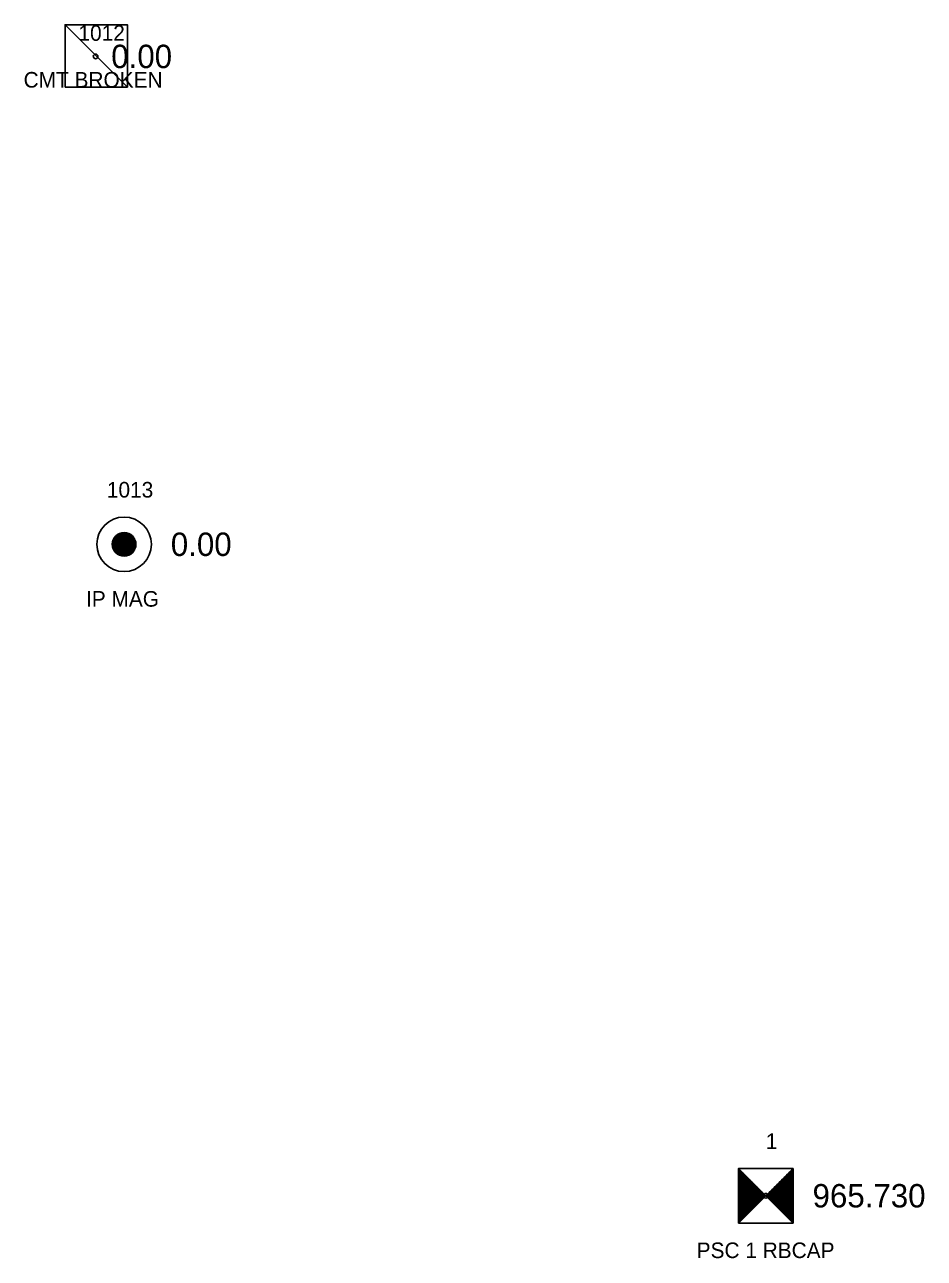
# Model space of a CAD drawing. Extents: x 1393163 to 1398407, y 1072670 to 1074651.
# Drawn here: x 1398130.1 to 1398187.8, y 1073408.2 to 1073487.3 of the extents above; entities that cross this region are included whole.
import ezdxf

# ---------------------------------------------------------------- set-up
doc = ezdxf.new("R2010")
doc.units = 0
for name, color, linetype in [('RD_EX_DV_Prop_txCode', 7, 'Continuous'), ('RD_EX_DV_PropPin', 7, 'Continuous'), ('RD_EX_TX_DV_Prop_ELEV', 7, 'Continuous'), ('RD_HC_Survey', 7, 'Continuous'), ('RD_HC_Survey_ELEV', 7, 'Continuous'), ('RD_HC_txCode', 7, 'Continuous'), ('RD_SMD_Locator', 7, 'Continuous')]:
    doc.layers.add(name, color=color, linetype=linetype)

msp = doc.modelspace()

# ---------------------------------------------------------------- linework, layer by layer
at = {"layer": 'RD_EX_DV_PropPin'}
for p, q in [((1398136.68, 1073483.307), (1398132.68, 1073487.307)), ((1398135.728, 1073453.781), (1398135.728, 1073454.174)), ((1398135.763, 1073453.679), (1398135.763, 1073454.275)), ((1398135.798, 1073453.608), (1398135.798, 1073454.347)), ((1398135.833, 1073453.551), (1398135.833, 1073454.404)), ((1398135.868, 1073453.503), (1398135.868, 1073454.452)), ((1398135.903, 1073453.462), (1398135.903, 1073454.492)), ((1398135.938, 1073453.427), (1398135.938, 1073454.528)), ((1398135.973, 1073453.395), (1398135.973, 1073454.56)), ((1398136.008, 1073453.368), (1398136.008, 1073454.587)), ((1398136.043, 1073453.343), (1398136.043, 1073454.612)), ((1398136.078, 1073453.321), (1398136.078, 1073454.634)), ((1398136.113, 1073453.302), (1398136.113, 1073454.653)), ((1398136.148, 1073453.285), (1398136.148, 1073454.67)), ((1398136.183, 1073453.27), (1398136.183, 1073454.685)), ((1398136.218, 1073453.257), (1398136.218, 1073454.698)), ((1398136.253, 1073453.246), (1398136.253, 1073454.709)), ((1398136.288, 1073453.237), (1398136.288, 1073454.718)), ((1398136.323, 1073453.229), (1398136.323, 1073454.725)), ((1398136.358, 1073453.224), (1398136.358, 1073454.731)), ((1398136.393, 1073453.22), (1398136.393, 1073454.735)), ((1398136.428, 1073453.217), (1398136.428, 1073454.738)), ((1398136.463, 1073453.216), (1398136.463, 1073454.738)), ((1398136.498, 1073453.217), (1398136.498, 1073454.738)), ((1398136.533, 1073453.22), (1398136.533, 1073454.735)), ((1398136.568, 1073453.224), (1398136.568, 1073454.731)), ((1398136.603, 1073453.229), (1398136.603, 1073454.725)), ((1398136.638, 1073453.237), (1398136.638, 1073454.718)), ((1398136.673, 1073453.246), (1398136.673, 1073454.709)), ((1398136.708, 1073453.257), (1398136.708, 1073454.698)), ((1398136.743, 1073453.27), (1398136.743, 1073454.685)), ((1398136.778, 1073453.285), (1398136.778, 1073454.67)), ((1398136.813, 1073453.302), (1398136.813, 1073454.653)), ((1398136.848, 1073453.321), (1398136.848, 1073454.634)), ((1398136.883, 1073453.343), (1398136.883, 1073454.612)), ((1398136.918, 1073453.368), (1398136.918, 1073454.587)), ((1398136.953, 1073453.395), (1398136.953, 1073454.56)), ((1398136.988, 1073453.427), (1398136.988, 1073454.528)), ((1398137.023, 1073453.462), (1398137.023, 1073454.492)), ((1398137.058, 1073453.503), (1398137.058, 1073454.452)), ((1398137.093, 1073453.551), (1398137.093, 1073454.404)), ((1398137.128, 1073453.608), (1398137.128, 1073454.347)), ((1398137.163, 1073453.679), (1398137.163, 1073454.275)), ((1398137.198, 1073453.781), (1398137.198, 1073454.174))]:
    msp.add_line(p, q, dxfattribs=at)
msp.add_lwpolyline([(1398132.68, 1073483.307), (1398132.68, 1073487.307), (1398136.68, 1073487.307), (1398136.68, 1073483.307)], close=True, dxfattribs=at)
for radius in [1.75, 0.761]:
    msp.add_circle((1398136.463, 1073453.977), radius, dxfattribs=at)
at = {"layer": 'RD_HC_Survey'}
for p, q in [((1398175.884, 1073413.941), (1398179.383, 1073410.442)), ((1398179.383, 1073413.941), (1398175.884, 1073410.442)), ((1398175.908, 1073413.917), (1398175.908, 1073410.466)), ((1398175.933, 1073413.892), (1398175.933, 1073410.491)), ((1398175.958, 1073413.867), (1398175.958, 1073410.516)), ((1398175.983, 1073413.842), (1398175.983, 1073410.541)), ((1398176.007, 1073413.818), (1398176.007, 1073410.565)), ((1398176.032, 1073413.793), (1398176.032, 1073410.59)), ((1398176.057, 1073413.768), (1398176.057, 1073410.615)), ((1398176.081, 1073413.744), (1398176.081, 1073410.639)), ((1398176.106, 1073413.719), (1398176.106, 1073410.664)), ((1398176.131, 1073413.694), (1398176.131, 1073410.689)), ((1398176.156, 1073413.669), (1398176.156, 1073410.714)), ((1398176.18, 1073413.645), (1398176.18, 1073410.738)), ((1398179.087, 1073413.645), (1398179.087, 1073410.738)), ((1398179.111, 1073413.669), (1398179.111, 1073410.714)), ((1398179.136, 1073413.694), (1398179.136, 1073410.689)), ((1398179.161, 1073413.719), (1398179.161, 1073410.664)), ((1398179.186, 1073413.744), (1398179.186, 1073410.639)), ((1398179.21, 1073413.768), (1398179.21, 1073410.615)), ((1398179.235, 1073413.793), (1398179.235, 1073410.59)), ((1398179.26, 1073413.818), (1398179.26, 1073410.565)), ((1398179.284, 1073413.842), (1398179.284, 1073410.541)), ((1398179.309, 1073413.867), (1398179.309, 1073410.516)), ((1398179.334, 1073413.892), (1398179.334, 1073410.491)), ((1398179.359, 1073413.917), (1398179.359, 1073410.466)), ((1398176.205, 1073413.62), (1398176.205, 1073410.763)), ((1398176.23, 1073413.595), (1398176.23, 1073410.788)), ((1398176.255, 1073413.57), (1398176.255, 1073410.813)), ((1398176.279, 1073413.546), (1398176.279, 1073410.837)), ((1398176.304, 1073413.521), (1398176.304, 1073410.862)), ((1398176.329, 1073413.496), (1398176.329, 1073410.887)), ((1398176.354, 1073413.471), (1398176.354, 1073410.912)), ((1398176.378, 1073413.447), (1398176.378, 1073410.936)), ((1398176.403, 1073413.422), (1398176.403, 1073410.961)), ((1398176.428, 1073413.397), (1398176.428, 1073410.986)), ((1398176.453, 1073413.372), (1398176.453, 1073411.011)), ((1398176.477, 1073413.348), (1398176.477, 1073411.035)), ((1398176.502, 1073413.323), (1398176.502, 1073411.06)), ((1398176.527, 1073413.298), (1398176.527, 1073411.085)), ((1398176.552, 1073413.273), (1398176.552, 1073411.11)), ((1398176.576, 1073413.249), (1398176.576, 1073411.134)), ((1398176.601, 1073413.224), (1398176.601, 1073411.159)), ((1398176.626, 1073413.199), (1398176.626, 1073411.184)), ((1398176.651, 1073413.174), (1398176.651, 1073411.209)), ((1398176.675, 1073413.15), (1398176.675, 1073411.233)), ((1398176.7, 1073413.125), (1398176.7, 1073411.258)), ((1398176.725, 1073413.1), (1398176.725, 1073411.283)), ((1398176.75, 1073413.075), (1398176.75, 1073411.308)), ((1398176.774, 1073413.051), (1398176.774, 1073411.332)), ((1398176.799, 1073413.026), (1398176.799, 1073411.357)), ((1398176.824, 1073413.001), (1398176.824, 1073411.382)), ((1398176.849, 1073412.976), (1398176.849, 1073411.407)), ((1398176.873, 1073412.952), (1398176.873, 1073411.431)), ((1398176.898, 1073412.927), (1398176.898, 1073411.456)), ((1398176.923, 1073412.902), (1398176.923, 1073411.481)), ((1398176.948, 1073412.877), (1398176.948, 1073411.506)), ((1398176.972, 1073412.853), (1398176.972, 1073411.53)), ((1398178.295, 1073412.853), (1398178.295, 1073411.53)), ((1398178.319, 1073412.877), (1398178.319, 1073411.506)), ((1398178.344, 1073412.902), (1398178.344, 1073411.481)), ((1398178.369, 1073412.927), (1398178.369, 1073411.456)), ((1398178.394, 1073412.952), (1398178.394, 1073411.431)), ((1398178.418, 1073412.976), (1398178.418, 1073411.407)), ((1398178.443, 1073413.001), (1398178.443, 1073411.382)), ((1398178.468, 1073413.026), (1398178.468, 1073411.357)), ((1398178.493, 1073413.051), (1398178.493, 1073411.332)), ((1398178.517, 1073413.075), (1398178.517, 1073411.308)), ((1398178.542, 1073413.1), (1398178.542, 1073411.283)), ((1398178.567, 1073413.125), (1398178.567, 1073411.258)), ((1398178.592, 1073413.15), (1398178.592, 1073411.233)), ((1398178.616, 1073413.174), (1398178.616, 1073411.209)), ((1398178.641, 1073413.199), (1398178.641, 1073411.184)), ((1398178.666, 1073413.224), (1398178.666, 1073411.159)), ((1398178.691, 1073413.249), (1398178.691, 1073411.134)), ((1398178.715, 1073413.273), (1398178.715, 1073411.11)), ((1398178.74, 1073413.298), (1398178.74, 1073411.085)), ((1398178.765, 1073413.323), (1398178.765, 1073411.06)), ((1398178.79, 1073413.348), (1398178.79, 1073411.035)), ((1398178.814, 1073413.372), (1398178.814, 1073411.011)), ((1398178.839, 1073413.397), (1398178.839, 1073410.986)), ((1398178.864, 1073413.422), (1398178.864, 1073410.961)), ((1398178.889, 1073413.447), (1398178.889, 1073410.936)), ((1398178.913, 1073413.471), (1398178.913, 1073410.912)), ((1398178.938, 1073413.496), (1398178.938, 1073410.887)), ((1398178.963, 1073413.521), (1398178.963, 1073410.862)), ((1398178.988, 1073413.546), (1398178.988, 1073410.837)), ((1398179.012, 1073413.57), (1398179.012, 1073410.813)), ((1398179.037, 1073413.595), (1398179.037, 1073410.788)), ((1398179.062, 1073413.62), (1398179.062, 1073410.763)), ((1398176.997, 1073412.828), (1398176.997, 1073411.555)), ((1398177.022, 1073412.803), (1398177.022, 1073411.58)), ((1398177.047, 1073412.778), (1398177.047, 1073411.605)), ((1398177.071, 1073412.754), (1398177.071, 1073411.629)), ((1398177.096, 1073412.729), (1398177.096, 1073411.654)), ((1398177.121, 1073412.704), (1398177.121, 1073411.679)), ((1398177.146, 1073412.679), (1398177.146, 1073411.704)), ((1398177.17, 1073412.655), (1398177.17, 1073411.728)), ((1398177.195, 1073412.63), (1398177.195, 1073411.753)), ((1398177.22, 1073412.605), (1398177.22, 1073411.778)), ((1398177.245, 1073412.58), (1398177.245, 1073411.803)), ((1398177.269, 1073412.556), (1398177.269, 1073411.827)), ((1398177.294, 1073412.531), (1398177.294, 1073411.852)), ((1398177.319, 1073412.506), (1398177.319, 1073411.877)), ((1398177.344, 1073412.481), (1398177.344, 1073411.902)), ((1398177.368, 1073412.457), (1398177.368, 1073411.926)), ((1398177.393, 1073412.432), (1398177.393, 1073411.951)), ((1398177.418, 1073412.407), (1398177.418, 1073411.976)), ((1398177.443, 1073412.382), (1398177.443, 1073412.001)), ((1398177.467, 1073412.358), (1398177.467, 1073412.025)), ((1398177.492, 1073412.333), (1398177.492, 1073412.05)), ((1398177.517, 1073412.308), (1398177.517, 1073412.075)), ((1398177.542, 1073412.283), (1398177.542, 1073412.1)), ((1398177.566, 1073412.259), (1398177.566, 1073412.124)), ((1398177.591, 1073412.234), (1398177.591, 1073412.149)), ((1398177.616, 1073412.209), (1398177.616, 1073412.174)), ((1398177.651, 1073412.209), (1398177.651, 1073412.174)), ((1398177.676, 1073412.234), (1398177.676, 1073412.149)), ((1398177.701, 1073412.259), (1398177.701, 1073412.124)), ((1398177.725, 1073412.283), (1398177.725, 1073412.1)), ((1398177.75, 1073412.308), (1398177.75, 1073412.075)), ((1398177.775, 1073412.333), (1398177.775, 1073412.05)), ((1398177.8, 1073412.358), (1398177.8, 1073412.025)), ((1398177.824, 1073412.382), (1398177.824, 1073412.001)), ((1398177.849, 1073412.407), (1398177.849, 1073411.976)), ((1398177.874, 1073412.432), (1398177.874, 1073411.951)), ((1398177.899, 1073412.457), (1398177.899, 1073411.926)), ((1398177.923, 1073412.481), (1398177.923, 1073411.902)), ((1398177.948, 1073412.506), (1398177.948, 1073411.877)), ((1398177.973, 1073412.531), (1398177.973, 1073411.852)), ((1398177.998, 1073412.556), (1398177.998, 1073411.827)), ((1398178.022, 1073412.58), (1398178.022, 1073411.803)), ((1398178.047, 1073412.605), (1398178.047, 1073411.778)), ((1398178.072, 1073412.63), (1398178.072, 1073411.753)), ((1398178.097, 1073412.655), (1398178.097, 1073411.728)), ((1398178.121, 1073412.679), (1398178.121, 1073411.704)), ((1398178.146, 1073412.704), (1398178.146, 1073411.679)), ((1398178.171, 1073412.729), (1398178.171, 1073411.654)), ((1398178.196, 1073412.754), (1398178.196, 1073411.629)), ((1398178.22, 1073412.778), (1398178.22, 1073411.605)), ((1398178.245, 1073412.803), (1398178.245, 1073411.58)), ((1398178.27, 1073412.828), (1398178.27, 1073411.555))]:
    msp.add_line(p, q, dxfattribs=at)
msp.add_lwpolyline([(1398179.383, 1073413.941), (1398175.884, 1073413.941), (1398175.884, 1073410.442), (1398179.383, 1073410.442)], close=True, dxfattribs=at)
at = {"layer": 'RD_SMD_Locator'}
for centre in [(1398134.641, 1073485.272), (1398136.463, 1073453.977), (1398177.634, 1073412.192)]:
    msp.add_circle(centre, 0.15, dxfattribs=at)

# ---------------------------------------------------------------- texts
at = {"layer": 'RD_EX_DV_Prop_txCode'}
for s, p in [('1012', (1398133.538, 1073486.272)), ('CMT BROKEN', (1398130.018, 1073483.272)), ('1013', (1398135.361, 1073456.977)), ('IP MAG', (1398134.022, 1073449.977))]:
    msp.add_text(s, height=1, dxfattribs=at).set_placement(p)
at = {"layer": 'RD_EX_TX_DV_Prop_ELEV'}
for p in [(1398135.641, 1073484.522), (1398139.463, 1073453.227)]:
    msp.add_text('0.00', height=1.5, dxfattribs=at).set_placement(p)
at = {"layer": 'RD_HC_Survey_ELEV'}
msp.add_text('965.730', height=1.5, dxfattribs=at).set_placement((1398180.634, 1073411.442))
at = {"layer": 'RD_HC_txCode'}
for s, p in [('1', (1398177.634, 1073415.192)), ('PSC 1 RBCAP', (1398173.2, 1073408.192))]:
    msp.add_text(s, height=1, dxfattribs=at).set_placement(p)

doc.saveas('drawing.dxf')
